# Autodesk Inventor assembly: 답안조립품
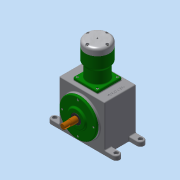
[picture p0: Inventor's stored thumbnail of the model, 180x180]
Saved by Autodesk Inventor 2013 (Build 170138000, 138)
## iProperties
Created: 2016-11
Part Number: 답안조립품
Document SubType Name: Assembly
Designer: Administrator
Mass: 5630.15 g
Surface Area: 4291.84 cm^2
Volume: 1587.81 cm^3
Density: 3.54585 g/cm^3
Author: Administrator
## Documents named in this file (16)
- C:\Users\Administrator\Desktop\361108v1008\답안조립품.iam
- C:\Users\Administrator\Desktop\361108v1008\본체.ipt
- C:\Users\Administrator\Desktop\361108v1008\메인크랭크축.ipt
- C:\Users\Administrator\Desktop\361108v1008\크랭크보조축.ipt
- C:\Users\Administrator\Desktop\361108v1008\베어링 20 x 47 x 14.ipt
- C:\Users\Administrator\Desktop\361108v1008\앞커버.ipt
- C:\Users\Administrator\Desktop\361108v1008\베어링 NA 4902.ipt
- C:\Users\Administrator\Desktop\361108v1008\오일 실 20 35 8.ipt
- C:\Users\Administrator\Desktop\361108v1008\볼트 M4 x 8.ipt
- C:\Users\Administrator\Desktop\361108v1008\커넥팅로드.ipt
- C:\Users\Administrator\Desktop\361108v1008\피스톤.ipt
- C:\Users\Administrator\Desktop\361108v1008\피스톤핀.ipt
- C:\Users\Administrator\Desktop\361108v1008\실린더.ipt
- C:\Users\Administrator\Desktop\361108v1008\실린더헤드.ipt
- C:\Users\Administrator\Desktop\361108v1008\가변스프링.ipt
- C:\Users\Administrator\Desktop\361108v1008\볼트 M5 x 20.ipt
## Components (15 placed, 5 different names)
1. 피스톤:1
2. 피스톤핀:1
3. 가변스프링:1
4. ISO 4762 M4 x 8:1
5. ISO 4762 M4 x 8:2
6. ISO 4762 M4 x 8:3
7. ISO 4762 M4 x 8:4
8. ISO 4762 M4 x 8:5
9. ISO 4762 M4 x 8:6
10. ISO 4762 M4 x 8:7
11. ISO 4762 M4 x 8:8
12. ISO 4762 M5 x 20:1
13. ISO 4762 M5 x 20:2
14. ISO 4762 M5 x 20:3
15. ISO 4762 M5 x 20:4
